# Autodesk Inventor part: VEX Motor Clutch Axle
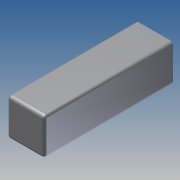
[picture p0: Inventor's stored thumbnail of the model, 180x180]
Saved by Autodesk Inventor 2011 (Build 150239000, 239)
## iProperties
Created: 2010-06
Part Number: VEX Motor Clutch Axle
Document SubType Name: Modeling
Designer: Phil
Density: 1 g/cm^3
Author: Phil
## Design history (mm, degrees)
sketch "Sketch1"
  geometry: L1 (-0.254, 0)-(-0.254, 2.667); L2 (2.667, -0.254)-(0, -0.254); L3 (2.921, 2.667)-(2.921, 0); L4 (0, 2.921)-(2.667, 2.921); A1 r 0.254 centre (0, 2.667) between (0, 2.921) and (-0.254, 2.667); A2 r 0.254 centre (0, 0) between (-0.254, 0) and (0, -0.254); A3 r 0.254 centre (2.667, 0) between (2.667, -0.254) and (2.921, 0); A4 r 0.254 centre (2.667, 2.667) between (2.921, 2.667) and (2.667, 2.921); 2 further points
  constraints: 8 end point, 8 point on circle, 4 centre point
extrude "Extrusion1" new body sketch "Sketch1" distance "d0" = 11.0236; taper "d1" = 0 deg
fillet "Fillet1" dims "d2" = 0.254
body "Solid1"
